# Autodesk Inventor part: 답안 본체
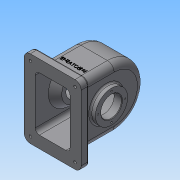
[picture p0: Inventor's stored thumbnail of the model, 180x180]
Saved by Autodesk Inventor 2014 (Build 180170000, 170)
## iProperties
Created: 2016-10
Part Number: 답안 본체
Material: 일반
Document SubType Name: Modeling
Designer: NET
Density: 1 g/cm^3
Appearance: 기본값
Mass: 429.752 g
Surface Area: 1201.17 cm^2
Volume: 429.752 cm^3
Author: NET
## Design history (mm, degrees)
sketch "스케치1"
  geometry: L1 (55, -75)-(-55, -75); L2 (-55, -75)-(-55, 75); L3 (-55, 75)-(55, 75); L4 (55, 75)-(55, -75); 1 further point
  constraints: 8 end point, 2 parallel, 1 horizontal, 1 perpendicular
  dimensions: "d0" = 150 distance of L1.end L2.end; "d1" = 110 distance of L1.start L1.end; "d2" = 55 distance from line of point (0, 0) L2; "d3" = 75 distance from line of point (0, 0) L1
extrude "돌출1" new body sketch "스케치1" distance "d4" = 15; taper "d5" = 0 deg
node "작업 평면1"
sketch "스케치2"
  geometry: L1 (75, 0)-(75, 80); L2 (17, 80)-(17, 7.723); L3 (133, 80)-(133, 7.723); L4 (17, 7.723)-(133, 7.723); A1 r 58 centre (75, 80) between (133, 80) and (17, 80)
  constraints: 8 end point, 2 parallel, 2 point on circle, 2 tangent, 1 centre point, 1 coincident, 1 perpendicular, 1 vertical
  dimensions: "d6" = 80 distance of L1.start L1.end; "d9" = 58 radius of A1; "d21" = 72.27659 distance from line of A1.centre L4
extrude "돌출2" join sketch "스케치2" stored distance "d11" = 77; taper "d12" = 0 deg
sketch "스케치3"
  geometry: L1 (17, 15)-(17, 80) reference; L2 (133, 80)-(133, 15) reference; L3 (0, 0)-(150, 0) reference; L4 (23, 0)-(23, 80); L5 (127, 80)-(127, 0); L6 (23, 0)-(127, 0); A1 r 58 centre (75, 80) between (133, 80) and (17, 80) reference; A2 r 52 centre (75, 80) between (127, 80) and (23, 80); 3 further points
  constraints: 6 end point, 2 point on circle, 2 point on line, 1 centre point, 1 collinear
  dimensions: "d13" = 6 radial gap between concentric circles of A1 A2; "d14" = 80 distance of L5.start L5.end; "d15" = 80 distance of L4.start L4.end; "d16" = 104 distance between parallel lines of L5 L4
extrude "돌출3" cut sketch "스케치3" stored distance "d17" = 67; taper "d18" = 0 deg
node "작업 평면2"
sketch "스케치4"
  geometry: 1 further point
fillet "모깎기1" dims "d19" = 13
fillet "모깎기2" dims "d20" = 8
sketch "스케치5"
  geometry: 1 further point
fillet "모깎기3" dims "d22" = 12
sketch "스케치7"
  geometry: L1 (-12, 0)-(-138, 0) reference; L2 (-133, 80)-(-133, 15) reference; L3 (-75, 0)-(-75, 65); C1 r 37.5 at (-75, 65)
  constraints: 2 end point, 1 centre point, 1 coincident, 1 parallel
  dimensions: "d39" = 65 distance of L3.start L3.end; "d40" = 75 diameter of C1
extrude "돌출4" join sketch "스케치7" distance "d41" = 5; taper "d42" = 0 deg
sketch "스케치8"
  geometry: L1 (120, 80)-(120, 15) reference; L2 (75, 0)-(75, 65); C1 r 31 at (75, 65)
  constraints: 2 end point, 1 centre point, 1 coincident, 1 parallel
  dimensions: "d43" = 65 distance of L2.start L2.end; "d44" = 62 diameter of C1
extrude "돌출5" join sketch "스케치8" distance "d45" = 10; taper "d46" = 0 deg
fillet "모깎기4" dims "d47" = 3
fillet "모깎기5" dims "d48" = 3
sketch "스케치9"
  geometry: C1 r 37.5 at (0, 0) reference; C2 r 20 at (0, 0); 1 further point
  constraints: 1 centre point, 1 coincident
  dimensions: "d49" = 40 diameter of C2
sketch "스케치11" dims "d55" = 58
  geometry: L1 (0, 0)-(0, 29); C1 r 37.5 at (0, 0) reference; 2 further points
  constraints: 2 coincident, 2 end point, 1 vertical, 1 vertical alignment, 2 other
hole "구멍1" sketch "스케치11" at (0, 29) diameter "d56" = 3; stored, may be unused: countersink angle "d60" = 90 deg, drill point angle "d62" = 118 deg; dims "d57" = 6, "d58" = 4, "d59" = 2, "d61" = 8
feature "스레드1" dims "d63" = 6, "d64" = 0
sketch "스케치12" dims "d68" = 52
  geometry: L1 (0, 0)-(0, 26); C1 r 31 at (0, 0) reference; 2 further points
  constraints: 2 coincident, 2 end point, 1 vertical, 1 vertical alignment, 2 other
hole "구멍2" sketch "스케치12" at (0, 26) diameter "d69" = 3; stored, may be unused: countersink angle "d73" = 90 deg, drill point angle "d75" = 118 deg; dims "d70" = 6, "d71" = 4, "d72" = 2, "d74" = 8
feature "스레드2" dims "d76" = 6, "d77" = 0
fillet "모깎기6" dims "d81" = 3
fillet "모깎기7" dims "d82" = 3
hole "구멍3" diameter "d85" = 5; stored, may be unused: countersink angle "d89" = 90 deg, drill point angle "d91" = 118 deg; dims "d83" = 10, "d84" = 10, "d86" = 6, "d87" = 12, "d88" = 5, "d90" = 8
node "작업 평면3"
sketch "스케치13"
  geometry: C1 r 6 at (0, 0); 1 further point
  constraints: 1 centre point, 1 coincident
  dimensions: "d93" = 12 diameter of C1
extrude "돌출8" join sketch "스케치13" stored distance "d94" = 15; taper "d95" = 0 deg
feature "면 기울기1" dims angle "d96" = 10 deg
fillet "모깎기8" dims "d97" = 3
hole "구멍4" diameter "d100" = 4.459; stored, may be unused: countersink angle "d104" = 90 deg, drill point angle "d106" = 118 deg; dims "d98" = 10, "d99" = 10, "d101" = 25, "d102" = 12, "d103" = 5, "d105" = 8
sketch "스케치14"
  geometry: L1 (68.5, -80)-(-17.5, -80) reference; L2 (-13, 0)-(-13, -62) reference; 2 further points
  constraints: 1 other
  dimensions: "d112" = 40 distance from line of L1 point (25.5, -40); "d113" = 38.5 distance from line of point (25.5, -40) L2
feature "엠보싱1" sketch "스케치14" dims "d11" = 77, "d114" = 0.5, "d115" = 0
sketch "스케치15"
  geometry: 1 further point
sketch "스케치16"
  geometry: L1 (12, 0)-(98, 0) reference; L2 (21.5, 65)-(35.5, 65); L3 (21.5, 124)-(21.5, 80) reference; L4 (21.5, 80)-(21.5, 0) reference; L5 (35.5, 65)-(35.5, 93); L6 (35.5, 93)-(21.5, 104.747); L7 (21.5, 104.747)-(21.5, 65); 1 further point
  constraints: 8 end point, 2 point on line, 1 parallel
  dimensions: "d125" = 65 distance between parallel lines of L1 L2; "d128" = 50 deg angle of L5 L6; "d129" = 28 distance of L2.end L5.end; "d130" = 14 horizontal distance of L5.end L6.end; "d131" = 14 distance of L2.start L2.end
revolve "회전6" sketch "스케치16" stored, may be unused: angle "d132" = 90 deg
extrude "돌출13" cut sketch "스케치9" stored distance "d133" = 10; taper "d134" = 0 deg
chamfer "모따기1" distance "d135" = 1; stored, may be unused: second distance "d136" = 2, angle "d137" = 45 deg
chamfer "모따기2" distance "d138" = 1; stored, may be unused: second distance "d139" = 2, angle "d140" = 45 deg
node "솔리드1"
pattern_circular "원형 패턴1" dims angle "d66" = 360 deg
pattern_circular "원형 패턴2" dims angle "d79" = 360 deg
mirror "대칭1"
mirror "대칭2"
other parameters: "d92" = -144
